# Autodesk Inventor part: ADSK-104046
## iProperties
Shininess: 0.0
Created: 2000-12
Part Number: ADSK-104046
Description: CRS 1/2" THK. x 10" x 12" LONG
Document SubType Name: Modeling
Stock Number: ADSK-104046
Density: 1 g/cm^3
Density: 0.0
Volumn: 0.0
Area: 0.0
PropertySet Name: Model Information
Control State: 0
Master: False
Checked Out: False
Author: gao
